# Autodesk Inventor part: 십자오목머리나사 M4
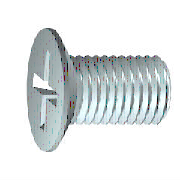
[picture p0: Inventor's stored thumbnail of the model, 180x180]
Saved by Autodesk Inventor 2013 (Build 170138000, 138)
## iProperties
IsCustomPart: 0
Created: 2012-02
Part Number: 십자오목머리나사 M4
Material: 강철, 연강
Description: 십자 오목 머리 나사
Document SubType Name: Modeling
Standard: KS B 1023
Designer: mduedu
Standards Organization: KS
Language: ko-KR
Size Designation: A  M 4 x 12 - H
Categories: <MemberInstance><Categories><Category DisplayName="조임쇠" InternalName="e4da775c-781d-43d5-af7c-5136215cf5a6" Mnemonic="FSTN"><Category DisplayName="볼트" InternalN
Density: 7.86 g/cm^3
Mass: 1.50482 g
Surface Area: 2.78557 cm^2
Volume: 0.191453 cm^3
Author: mduedu
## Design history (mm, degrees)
body "Solid1"
sketch "스케치1"
  geometry: L1 (2.6, 0)-(12, 0); L2 (12, 0)-(12, 2); L3 (12, 2)-(4.1, 2); L4 (4.1, 2)-(3.671, 1.785); L5 (3.671, 1.785)-(2.7, 1.785); L6 (0, 4.2)-(0, 2.4); L7 (0, 2.4)-(1.801, 1.502); L8 (1.801, 1.502)-(2.6, 0); L9 (-2.4, 0)-(14.4, 0) reference; L10 (0, -0.84)-(0, 5.04) reference; L11 (0, 4.2)-(0.285, 4.2); L12 (0.285, 4.2)-(2.7, 1.785); L13 (4.1, 2)-(2.485, 2)
  constraints: 22 end point, 3 parallel, 3 perpendicular, 2 collinear, 1 horizontal, 1 point on line
  dimensions: "d1" = 7.9 distance of L2.end L3.end (= GEL); "d2" = 4 diameter of L3 L1 (= GD); "d3" = 3.57058 diameter of L5 L1 (= BDM); "d4" = 4.8 diameter of L6.end L1 (= SDM); "d5" = 26.5 deg angle of L7 L1; "d6" = 62 deg angle of L8 L1; "d7" = 2.6 distance from line of L1.start L6 (= INTI); "d8" = 0.42941 horizontal distance of L4.end L3.end (= GAL); "d12" = 8.4 diameter of L11 L1 (= KOD); "d13" = 45 deg angle of L12 L1 (= 0.5 x SEWI); "d15" = 12 distance between parallel lines of L2 L6 (= NLG); "d24" = 2.7 distance from line of L5.end L6 (= KOH)
revolve "본체" stored, may be unused: angle "d16" = 90 deg
sketch "스케치2"
  geometry: L1 (0, 2.4)-(0, 0); L2 (0, 0)-(2.4, 0); L3 (0, 0)-(1.697, 1.697); L4 (0.312, 2.38)-(0.408, 0.734); L5 (2.38, 0.312)-(0.734, 0.408); L6 (0, -5.88)-(0, 5.88) reference; L7 (-5.88, 0)-(5.88, 0) reference; L8 (2.38, -0.312)-(0.734, -0.408); L9 (0.312, -2.38)-(0.408, -0.734); L10 (-0.312, -2.38)-(-0.408, -0.734); L11 (-2.38, -0.312)-(-0.734, -0.408); L12 (-2.38, 0.312)-(-0.734, 0.408); L13 (-0.312, 2.38)-(-0.408, 0.734); A1 r 0.72 centre (0, 0) between (0.72, 0) and (0, 0.72); A2 r 0.84 centre (0, 0) between (0.84, 0) and (0, 0.84); A3 r 2.4 centre (0, 0) between (2.38, 0.312) and (0.312, 2.38); A4 r 2.4 centre (0, 0) between (0.312, 2.38) and (0, 2.4); A5 r 2.4 centre (0, 0) between (2.4, 0) and (2.38, 0.312); A6 r 2.4 centre (0, 0) between (0, -2.4) and (0.312, -2.38); A7 r 2.4 centre (0, 0) between (0.312, -2.38) and (2.38, -0.312); A8 r 2.4 centre (0, 0) between (2.38, -0.312) and (2.4, 0); A9 r 2.4 centre (0, 0) between (0, 2.4) and (-0.312, 2.38); A10 r 2.4 centre (0, 0) between (-0.312, 2.38) and (-2.38, 0.312); A11 r 2.4 centre (0, 0) between (-2.38, 0.312) and (-2.4, 0); A12 r 2.4 centre (0, 0) between (-2.4, 0) and (-2.38, -0.312); A13 r 2.4 centre (0, 0) between (-2.38, -0.312) and (-0.312, -2.38); A14 r 2.4 centre (0, 0) between (-0.312, -2.38) and (0, -2.4); A15 r 0.347 centre (0.755, 0.755) between (0.408, 0.734) and (0.734, 0.408); A16 r 0.347 centre (0.755, -0.755) between (0.734, -0.408) and (0.408, -0.734); A17 r 0.347 centre (-0.755, -0.755) between (-0.408, -0.734) and (-0.734, -0.408); A18 r 0.347 centre (-0.755, 0.755) between (-0.734, 0.408) and (-0.408, 0.734); 3 further points
  constraints: 41 point on circle, 22 end point, 22 symmetric about line, 18 centre point, 11 coincident, 4 point on line, 3 tangent, 2 collinear, 1 perpendicular, 1 vertical, 19 other
  dimensions: "d17" = 1.44 diameter of A1 (= 0.3 x SDM); "d18" = 1.68 diameter of A2 (= 0.35 x SDM); "d19" = 4.8 diameter of A3 (= SDM); "d20" = 45 deg angle of L3 L2; "d21" = 0.3115 distance from line of L4.start L1 (= 0.5 x SBR)
extrude "슬롯" join sketch "스케치2" taper "d22" = 5 deg; stored distance "d79" = 25.4
fillet "모깎기1" dims "d23" = 0.1246 (= 0.2 x SBR)
feature "스레드" dims "d10" = 7.9 (= GEL), "d11" = 0
chamfer "모따기1" distance "d25" = 0.42941 (= -0.5 x SPD + 0.5 x GD); stored, may be unused: second distance "d26" = 0.21471 (= 0.5 x GAL), angle "d88" = 45 deg
workplane "Work Plane2"
other parameters: "NLG" = 12 [user parameter; used in 1 equation term], "GEL" = 7.9 [user parameter; used in 2 equation terms], "GAL" = 0.42941 (= 0.61345 x PTC) [user parameter; used in 3 equation terms], "SPD" = 3.14117 (= NND - 1.2269 x PTC) [user parameter; used in 1 equation term], "KOD" = 8.4 [user parameter; used in 1 equation term], "KOH" = 2.7 [user parameter; used in 1 equation term], "SBR" = 0.623 [user parameter; used in 2 equation terms], "INTI" = 2.6 [user parameter; used in 1 equation term], "SDM" = 4.8 [user parameter; used in 5 equation terms], "GD" = 4 (= NND) [user parameter; used in 2 equation terms], "BDM" = 3.57058 (= NND - GAL) [user parameter; used in 1 equation term], "SEWI" = 90 deg [user parameter; used in 1 equation term], "d9" = 4.8 (= SDM), "d27" = 0, "d91" = 0, "d92" = 0, "GUL" = 0.42941 (= 0.61345 x PTC) [user parameter], "TOA" = 30 deg [user parameter], "EPV" = 4.7 [user parameter], "THREADDIA" = 4 [user parameter; used in 1 equation term], "TPU" = 14.28571 (computed from PTC) [user parameter], "PTC" = 0.7 [user parameter; used in 5 equation terms], "NND" = 4 [user parameter; used in 3 equation terms], "GD1" = 3.14117 (= THREADDIA - 1.2269 x PTC) [user parameter]
